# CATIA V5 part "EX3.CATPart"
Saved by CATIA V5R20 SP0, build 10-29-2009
Part number: EX3
Bounding box of the stored display mesh (mm): x 0 to 124.994, y 0 to 101.994, z 0 to 0
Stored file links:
  E:\Nouveau dossier\tarek\mécaniquee\FAO\CATIA\CATIA CATIA\EX3.CATPart
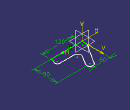
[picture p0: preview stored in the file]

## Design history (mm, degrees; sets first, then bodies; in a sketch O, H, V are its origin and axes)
Body1 (main body)
  Sketch1 on zx-plane, origin (0, 0, 0), H (-1, 0, 0), V (0, 0, 1)
  Sketch2 on xy-plane, origin (0, 0, 0), H (1, 0, 0), V (0, 1, 0)
    line L1 (0, 0) -> (120, 0)
    point P2 (115, 20)
    line L2 (120, 0) -> (120, 11.3397)
    arc A1 centre (115, 20) radius 10 from (120, 11.3397) to (115, 30) ccw
    point P5 (12, 15)
    line L3 (0, 15) -> (0, 0)
    point P7 (60, 90)
    line L4 (1.8927, 21.4686) -> (49.8927, 96.4686)
    arc A2 centre (12, 15) radius 12 from (1.8927, 21.4686) to (0, 15) ccw
    arc A3 centre (60, 90) radius 12 from (69.9626, 83.3107) to (49.8927, 96.4686) ccw
    arc A4 centre (61.4289, 44) radius 14 from (49.6371, 51.5468) to (60, 30.0731) ccw
    line L5 (115, 30) -> (60, 30.0731)
    line L6 (69.9626, 83.3107) -> (49.6371, 51.5468)
    length L1 = 120
    distance P2 L1 = 20
    distance P5 L1 = 15
    distance V P5 = 12
    distance P7 L3 = 60
    distance P7 L1 = 90
    horizontal: L1 H
    vertical: L2 V, L3 V
    tangency: A2 L3, A3 L4, A2 L4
